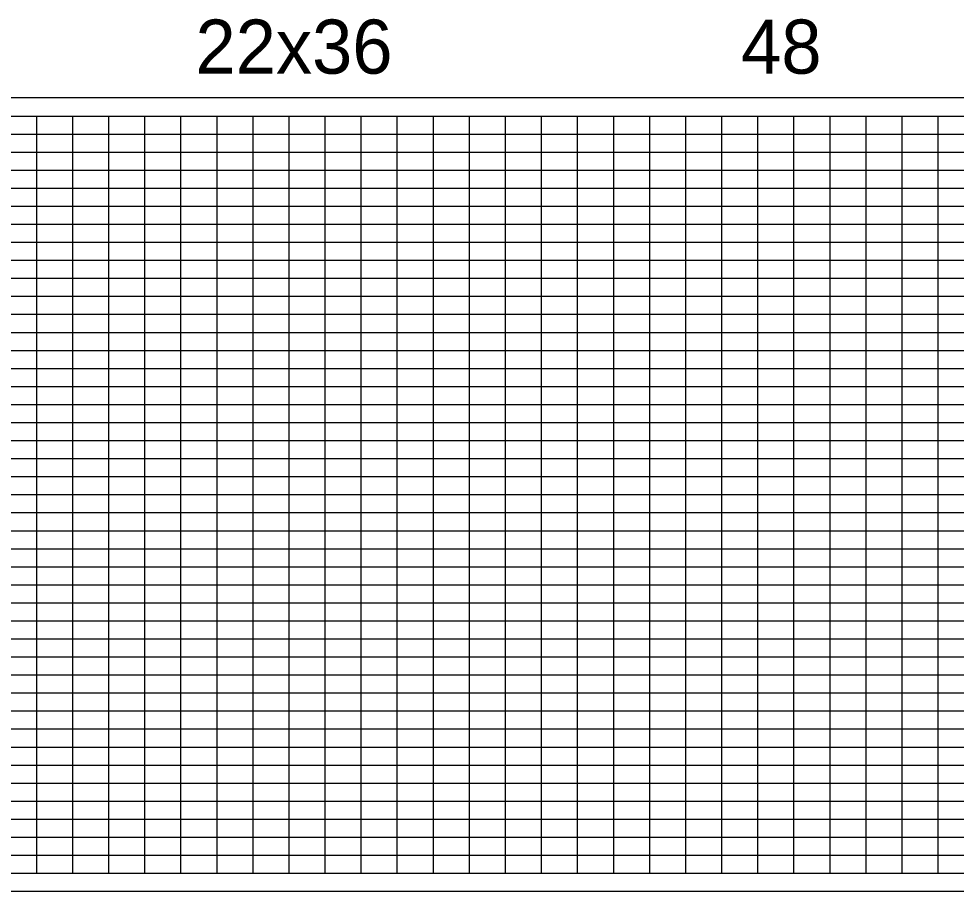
# Model space of a CAD drawing. Extents: x 1873632 to 1926512, y 813126 to 836257.
# Drawn here: x 1901038 to 1902338, y 823217 to 824426 of the extents above; entities that cross this region are included whole.
import ezdxf

# ---------------------------------------------------------------- set-up
doc = ezdxf.new("R2010")
doc.units = 0
doc.layers.add('RD_PD_WallFill', color=7, linetype='Continuous')
doc.layers.add('RD_SHT_IplotShp', color=7, linetype='Continuous')

msp = doc.modelspace()

# ---------------------------------------------------------------- linework, layer by layer
at = {"layer": 'RD_PD_WallFill'}
for p, q in [((1899713.1, 824291.6), (1905063.1, 824291.6)), ((1899713.1, 824291.6), (1901463.1, 824291.6)), ((1901063.1, 823241.6), (1901063.1, 824291.6)), ((1901063.1, 823241.6), (1901063.1, 824291.6)), ((1901113.1, 823241.6), (1901113.1, 824291.6)), ((1901113.1, 823241.6), (1901113.1, 824291.6)), ((1901163.1, 823241.6), (1901163.1, 824291.6)), ((1901163.1, 823241.6), (1901163.1, 824291.6)), ((1901213.1, 823241.6), (1901213.1, 824291.6)), ((1901213.1, 823241.6), (1901213.1, 824291.6)), ((1901263.1, 823241.6), (1901263.1, 824291.6)), ((1901263.1, 823241.6), (1901263.1, 824291.6)), ((1901313.1, 823241.6), (1901313.1, 824291.6)), ((1901313.1, 823241.6), (1901313.1, 824291.6)), ((1901363.1, 823241.6), (1901363.1, 824291.6)), ((1901363.1, 823241.6), (1901363.1, 824291.6)), ((1901413.1, 823241.6), (1901413.1, 824291.6)), ((1901413.1, 823241.6), (1901413.1, 824291.6)), ((1901463.1, 823241.6), (1901463.1, 824291.6)), ((1901463.1, 823241.6), (1901463.1, 824291.6)), ((1901513.1, 823241.6), (1901513.1, 824291.6)), ((1901513.1, 823241.6), (1901513.1, 824291.6)), ((1901563.1, 823241.6), (1901563.1, 824291.6)), ((1901563.1, 823241.6), (1901563.1, 824291.6)), ((1901613.1, 823241.6), (1901613.1, 824291.6)), ((1901613.1, 823241.6), (1901613.1, 824291.6)), ((1901663.1, 823241.6), (1901663.1, 824291.6)), ((1901663.1, 823241.6), (1901663.1, 824291.6)), ((1901713.1, 823241.6), (1901713.1, 824291.6)), ((1901713.1, 823241.6), (1901713.1, 824291.6)), ((1901763.1, 823241.6), (1901763.1, 824291.6)), ((1901763.1, 823241.6), (1901763.1, 824291.6)), ((1901813.1, 823241.6), (1901813.1, 824291.6)), ((1901813.1, 823241.6), (1901813.1, 824291.6)), ((1901863.1, 823241.6), (1901863.1, 824291.6)), ((1901863.1, 823241.6), (1901863.1, 824291.6)), ((1901913.1, 823241.6), (1901913.1, 824291.6)), ((1901913.1, 823241.6), (1901913.1, 824291.6)), ((1901963.1, 823241.6), (1901963.1, 824291.6)), ((1901963.1, 823241.6), (1901963.1, 824291.6)), ((1902013.1, 823241.6), (1902013.1, 824291.6)), ((1902013.1, 823241.6), (1902013.1, 824291.6)), ((1902063.1, 823241.6), (1902063.1, 824291.6)), ((1902063.1, 823241.6), (1902063.1, 824291.6)), ((1902113.1, 823241.6), (1902113.1, 824291.6)), ((1902113.1, 823241.6), (1902113.1, 824291.6)), ((1902163.1, 823241.6), (1902163.1, 824291.6)), ((1902163.1, 823241.6), (1902163.1, 824291.6)), ((1902213.1, 823241.6), (1902213.1, 824291.6)), ((1902213.1, 823241.6), (1902213.1, 824291.6)), ((1902263.1, 823241.6), (1902263.1, 824291.6)), ((1902263.1, 823241.6), (1902263.1, 824291.6)), ((1902313.1, 823241.6), (1902313.1, 824291.6)), ((1902313.1, 823241.6), (1902313.1, 824291.6)), ((1900163.1, 824266.6), (1905063.1, 824266.6)), ((1900163.1, 824266.6), (1905063.1, 824266.6)), ((1900163.1, 824241.6), (1905063.1, 824241.6)), ((1900163.1, 824216.6), (1905063.1, 824216.6)), ((1900163.1, 824191.6), (1905063.1, 824191.6)), ((1900163.1, 824166.6), (1905063.1, 824166.6)), ((1899713.1, 824141.6), (1905063.1, 824141.6)), ((1899713.1, 824116.6), (1905063.1, 824116.6)), ((1899713.1, 824091.6), (1905063.1, 824091.6)), ((1899713.1, 824066.6), (1905063.1, 824066.6)), ((1899713.1, 824041.6), (1905063.1, 824041.6)), ((1899713.1, 824016.6), (1905063.1, 824016.6)), ((1899713.1, 823991.6), (1905063.1, 823991.6)), ((1899713.1, 823966.6), (1905063.1, 823966.6)), ((1899713.1, 823941.6), (1905063.1, 823941.6)), ((1899713.1, 823916.6), (1905063.1, 823916.6)), ((1899713.1, 823891.6), (1905063.1, 823891.6)), ((1899713.1, 823866.6), (1905063.1, 823866.6)), ((1899713.1, 823841.6), (1905063.1, 823841.6)), ((1899713.1, 823816.6), (1905063.1, 823816.6)), ((1899713.1, 823791.6), (1905063.1, 823791.6)), ((1899713.1, 823766.6), (1905063.1, 823766.6)), ((1899713.1, 823741.6), (1905063.1, 823741.6)), ((1899713.1, 823716.6), (1905063.1, 823716.6)), ((1899713.1, 823691.6), (1905063.1, 823691.6)), ((1899713.1, 823666.6), (1905063.1, 823666.6)), ((1899713.1, 823641.6), (1905063.1, 823641.6)), ((1899713.1, 823616.6), (1905063.1, 823616.6)), ((1899713.1, 823591.6), (1905063.1, 823591.6)), ((1899713.1, 823566.6), (1905063.1, 823566.6)), ((1899713.1, 823541.6), (1905063.1, 823541.6)), ((1899713.1, 823516.6), (1905063.1, 823516.6)), ((1899713.1, 823491.6), (1905063.1, 823491.6)), ((1899713.1, 823466.6), (1905063.1, 823466.6)), ((1899713.1, 823441.6), (1905063.1, 823441.6)), ((1899713.1, 823416.6), (1905063.1, 823416.6)), ((1899713.1, 823391.6), (1905063.1, 823391.6)), ((1899713.1, 823366.6), (1905063.1, 823366.6)), ((1899713.1, 823341.6), (1905063.1, 823341.6)), ((1899713.1, 823316.6), (1905063.1, 823316.6)), ((1899713.1, 823291.6), (1905063.1, 823291.6)), ((1899713.1, 823266.6), (1905063.1, 823266.6)), ((1899713.1, 823241.6), (1905063.1, 823241.6)), ((1899713.1, 823241.6), (1905063.1, 823241.6))]:
    msp.add_line(p, q, dxfattribs=at)
at = {"layer": 'RD_SHT_IplotShp'}
msp.add_lwpolyline([(1899688.1, 823216.6), (1905088.1, 823216.6), (1905088.1, 824316.6), (1899688.1, 824316.6)], close=True, dxfattribs=at)

# ---------------------------------------------------------------- texts
at = {"layer": 'RD_PD_WallFill'}
for s, p in [('22x36', (1901283.2, 824350.3)), ('22x36', (1901283.2, 824350.3)), ('48', (1902039.8, 824350.3)), ('48', (1902039.8, 824350.3))]:
    msp.add_text(s, height=75, dxfattribs=at).set_placement(p)

doc.saveas('drawing.dxf')
